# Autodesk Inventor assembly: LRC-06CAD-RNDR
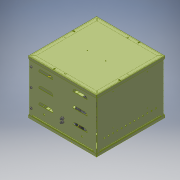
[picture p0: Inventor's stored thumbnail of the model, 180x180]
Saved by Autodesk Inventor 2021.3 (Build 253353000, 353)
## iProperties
Part Number: LRC-06CAD-RNDR
Document SubType Name: Assembly
Designer: JChurch
Author: JChurch
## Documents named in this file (6)
- X:\Revit Files\0000-Un-Zipped\COB\LRC-06CAD-RND\LRC-06CAD-RNDR.iam
- X:\INVENTOR\830\830399-00-00.ipt
- X:\INVENTOR\881\881035-00-00.iam
- X:\INVENTOR\830\830402-00-00.ipt
- X:\INVENTOR\KIRLIN_ENG\725\725075-00-00.ipt
- X:\INVENTOR\750\750300-01-XX.iam
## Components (5 placed, 5 different names)
1. 830399-00-00:1 — Mate:1, Mate:2, Mate:3, Mate:4, Mate:5, Angle:1, Insert:1
2. 881035-00-00:1 [sub-assembly] — Mate:4, Mate:5, Angle:1, Mate:6, Mate:7, Angle:2
3. 830402-00-00:1 — Mate:6, Mate:7, Angle:2
4. 725075-00-00:1 — Mate:8, Mate:9, Mate:10
5. 750300-01-XX:1 [sub-assembly] — Mate:8, Mate:9, Mate:10, Insert:1
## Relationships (13: Mate 10, Angle 2, Insert 1)
- Mate:1: 830399-00-00:1
- Mate:2: 830399-00-00:1
- Mate:3: 830399-00-00:1
- Mate:4: 830399-00-00:1 ↔ 881035-00-00:1
- Mate:5: 830399-00-00:1 ↔ 881035-00-00:1
- Angle:1: 830399-00-00:1 ↔ 881035-00-00:1
- Mate:6: 881035-00-00:1 ↔ 830402-00-00:1
- Mate:7: 881035-00-00:1 ↔ 830402-00-00:1
- Angle:2: 881035-00-00:1 ↔ 830402-00-00:1
- Mate:8: 725075-00-00:1 ↔ 750300-01-XX:1
- Mate:9: 725075-00-00:1 ↔ 750300-01-XX:1
- Mate:10: 725075-00-00:1 ↔ 750300-01-XX:1
- Insert:1: 830399-00-00:1 ↔ 750300-01-XX:1
